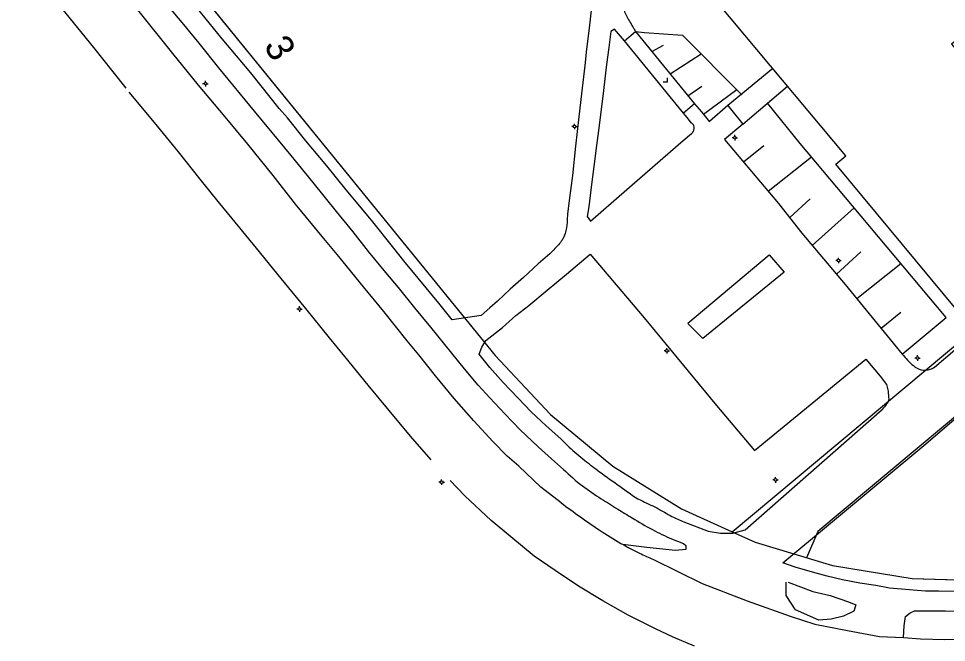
# Model space of a CAD drawing. Extents: x 1517229 to 1518128, y 6494851 to 6495271.
# Drawn here: x 1517641.4 to 1517777.6, y 6494938.3 to 6495029.8 of the extents above; entities that cross this region are included whole.
import ezdxf

# ---------------------------------------------------------------- set-up
doc = ezdxf.new("R2010")
doc.units = 0
doc.layers.add('Karta', color=7, linetype='Continuous')

msp = doc.modelspace()

# ---------------------------------------------------------------- linework, layer by layer
at = {"layer": 'Karta'}
for p, q in [((1517746.18, 6494954.49), (1517858.73, 6495048.55)), ((1517657.21, 6495046.87), (1517711.4, 6494980.36)), ((1517864, 6495042.53), (1517758.73, 6494954.55)), ((1517734.39, 6495024.95), (1517736.09, 6495025.88)), ((1517737.06, 6495021.68), (1517741.64, 6495024.6)), ((1517668.85, 6495020.44), (1517668.85, 6495020.64)), ((1517668.65, 6495020.24), (1517668.45, 6495020.24)), ((1517668.85, 6495020.04), (1517668.85, 6495019.84)), ((1517669.05, 6495020.24), (1517669.25, 6495020.24)), ((1517739.68, 6495018.48), (1517741.72, 6495019.9)), ((1517741.98, 6495015.75), (1517746.84, 6495019.4)), ((1517745.55, 6495017.02), (1517742.85, 6495014.7)), ((1517722.83, 6495013.96), (1517722.63, 6495013.96)), ((1517723.03, 6495014.16), (1517723.03, 6495014.36)), ((1517723.03, 6495013.76), (1517723.03, 6495013.56)), ((1517723.23, 6495013.96), (1517723.43, 6495013.96)), ((1517747.75, 6495014.28), (1517745.05, 6495012.04)), ((1517746.56, 6495012.52), (1517746.56, 6495012.72)), ((1517745.07, 6495012.05), (1517753, 6495002.66)), ((1517746.36, 6495012.32), (1517746.16, 6495012.32)), ((1517746.56, 6495012.12), (1517746.56, 6495011.92)), ((1517746.76, 6495012.32), (1517746.96, 6495012.32)), ((1517747.83, 6495008.78), (1517750.81, 6495011.15)), ((1517751.45, 6495004.49), (1517757.8, 6495009.53)), ((1517754.62, 6495000.59), (1517757.64, 6495003.37)), ((1517757.92, 6494996.52), (1517764.06, 6495002.02)), ((1517721.85, 6494992.31), (1517725.35, 6494995.22)), ((1517761.48, 6494992.29), (1517765.06, 6494995.58)), ((1517761.77, 6494994.49), (1517761.77, 6494994.69)), ((1517761.57, 6494994.29), (1517761.37, 6494994.29)), ((1517761.77, 6494994.09), (1517761.77, 6494993.89)), ((1517761.97, 6494994.29), (1517762.17, 6494994.29)), ((1517764.46, 6494988.7), (1517770.92, 6494993.87)), ((1517682.48, 6494987.18), (1517682.28, 6494987.18)), ((1517682.68, 6494987.38), (1517682.68, 6494987.58)), ((1517682.68, 6494986.98), (1517682.68, 6494986.78)), ((1517682.88, 6494987.18), (1517683.08, 6494987.18)), ((1517768.03, 6494984.35), (1517770.92, 6494986.72)), ((1517736.4, 6494981.06), (1517736.2, 6494981.06)), ((1517736.6, 6494981.26), (1517736.6, 6494981.46)), ((1517736.8, 6494981.06), (1517737, 6494981.06)), ((1517711.4, 6494980.36), (1517719.49, 6494971.68)), ((1517736.6, 6494980.86), (1517736.6, 6494980.66)), ((1517773.18, 6494979.99), (1517772.98, 6494979.99)), ((1517773.38, 6494980.19), (1517773.38, 6494980.39)), ((1517773.38, 6494979.79), (1517773.38, 6494979.59)), ((1517773.58, 6494979.99), (1517773.78, 6494979.99)), ((1517719.49, 6494971.68), (1517728.65, 6494964.14)), ((1517748.08, 6494954.76), (1517768.2, 6494972.45)), ((1517722.24, 6494966.93), (1517721.01, 6494968.14)), ((1517728.65, 6494964.14), (1517738.73, 6494957.86)), ((1517703.53, 6494961.98), (1517703.53, 6494962.18)), ((1517752.35, 6494962.1), (1517752.15, 6494962.1)), ((1517752.55, 6494962.3), (1517752.55, 6494962.5)), ((1517752.75, 6494962.1), (1517752.95, 6494962.1)), ((1517703.33, 6494961.78), (1517703.13, 6494961.78)), ((1517703.53, 6494961.58), (1517703.53, 6494961.38)), ((1517703.73, 6494961.78), (1517703.93, 6494961.78)), ((1517752.55, 6494961.9), (1517752.55, 6494961.7)), ((1517738.73, 6494957.86), (1517746.18, 6494954.49)), ((1517746.18, 6494954.49), (1517749.54, 6494952.96)), ((1517758.73, 6494954.55), (1517757.07, 6494950.69)), ((1517749.54, 6494952.96), (1517760.9, 6494949.53)), ((1517760.9, 6494949.53), (1517772.62, 6494947.63)), ((1517772.62, 6494947.63), (1517784.48, 6494947.28))]:
    msp.add_line(p, q, dxfattribs=at)
for points in [[(1517734.98, 6495043.01), (1517776.72, 6495077.67), (1517783.24, 6495069.88), (1517783.9, 6495070.37), (1517795.96, 6495055.9), (1517795.29, 6495055.3), (1517801.2, 6495048.09), (1517781.99, 6495032.2), (1517783.57, 6495030.27), (1517778.38, 6495026.04), (1517786.33, 6495016.68), (1517792.23, 6495021.58), (1517801.35, 6495010.73), (1517789.98, 6495001.11), (1517792.38, 6494998.21), (1517779.06, 6494987.16), (1517761.38, 6495008.42), (1517762.85, 6495009.67), (1517734.97, 6495043.01)], [(1517657.21, 6495046.87), (1517711.4, 6494980.36), (1517719.49, 6494971.68), (1517728.65, 6494964.14), (1517738.73, 6494957.86)], [(1517657.21, 6495019.59), (1517655.3, 6495021.99), (1517652.46, 6495025.53), (1517648.43, 6495030.54), (1517644.3, 6495035.55), (1517641.43, 6495039.12)], [(1517676.06, 6495016.19), (1517670.83, 6495022.55), (1517667.92, 6495026.2), (1517665.44, 6495029.21), (1517662.49, 6495032.75), (1517660.15, 6495035.66)], [(1517679.66, 6495016.62), (1517675.52, 6495021.82), (1517671.32, 6495026.83), (1517667.5, 6495031.52), (1517663.82, 6495035.97)], [(1517725.9, 6495034.88), (1517725.54, 6495031.49), (1517725.18, 6495028.4), (1517724.79, 6495025.32), (1517724.53, 6495022.91)], [(1517667.85, 6495020.03), (1517664.09, 6495024.69), (1517658.94, 6495031.07), (1517657.21, 6495033.2)], [(1517730.39, 6495026.54), (1517728.89, 6495028.25), (1517728.37, 6495027.88), (1517728.08, 6495025.55), (1517727.75, 6495023.06)], [(1517730.39, 6495026.54), (1517732.01, 6495027.91), (1517731.99, 6495027.88), (1517740.66, 6495017.28), (1517739.01, 6495015.93), (1517730.39, 6495026.54)], [(1517731.99, 6495027.89), (1517733.29, 6495027.73), (1517738.9, 6495027.34), (1517747.61, 6495018.63)], [(1517724.53, 6495022.91), (1517724.07, 6495018.76), (1517723.68, 6495015.36), (1517723.16, 6495011.09)], [(1517727.75, 6495023.06), (1517727.2, 6495018.42), (1517726.56, 6495013.37), (1517726.24, 6495011.19)], [(1517752.13, 6495022.48), (1517745.55, 6495017.02), (1517747.75, 6495014.28), (1517754.31, 6495019.88)], [(1517736.07, 6495020.5), (1517736.67, 6495020.5), (1517736.67, 6495021.1)], [(1517682.08, 6495002.58), (1517678.78, 6495006.78), (1517675.07, 6495011.37), (1517671.74, 6495015.4), (1517667.85, 6495020.03)], [(1517670.71, 6495002.98), (1517668.1, 6495006.22), (1517664.91, 6495010.25), (1517661.37, 6495014.53), (1517657.67, 6495019.01)], [(1517696.49, 6494996.12), (1517693.23, 6495000.2), (1517689.52, 6495004.65), (1517686.68, 6495008.19), (1517683.6, 6495011.86), (1517680.9, 6495015.23), (1517679.66, 6495016.62)], [(1517740.66, 6495017.28), (1517741.68, 6495016.13), (1517742.84, 6495014.64)], [(1517763.83, 6495002.3), (1517756.18, 6495011.48), (1517751.42, 6495017.33)], [(1517692.77, 6494995.63), (1517690.53, 6494998.51), (1517688.08, 6495001.49), (1517684.65, 6495005.73), (1517681.46, 6495009.69), (1517678.63, 6495013.07), (1517676.06, 6495016.19)], [(1517740.2, 6495014.47), (1517739.56, 6495015.26), (1517739.01, 6495015.93)], [(1517725.39, 6495000.07), (1517732.61, 6495006.4), (1517738.98, 6495011.89), (1517740.22, 6495012.93)], [(1517723.16, 6495011.09), (1517722.72, 6495006.76), (1517722.33, 6495003.83), (1517722, 6495001.16), (1517721.97, 6495000.25)], [(1517726.24, 6495011.19), (1517725.86, 6495008.08), (1517725.47, 6495005.05), (1517725.16, 6495002.17), (1517724.87, 6495000.74), (1517725.39, 6495000.07)], [(1517753.6, 6494949.92), (1517774.58, 6494967.4), (1517787.02, 6494978.07), (1517817.61, 6495004.85), (1517813.1, 6495011.01)], [(1517687.06, 6494982.93), (1517683.6, 6494987.27), (1517679.99, 6494991.65), (1517676.35, 6494996.13), (1517672.78, 6495000.44), (1517670.71, 6495002.98)], [(1517698.47, 6494982.51), (1517695.05, 6494986.81), (1517692.08, 6494990.42), (1517688.43, 6494994.91), (1517686.24, 6494997.54), (1517682.08, 6495002.58)], [(1517753, 6495002.66), (1517756.42, 6494998.31), (1517762.74, 6494990.79), (1517771.13, 6494980.58)], [(1517771.13, 6494980.58), (1517777.61, 6494985.92), (1517763.83, 6495002.3)], [(1517719.43, 6494995.29), (1517717.68, 6494993.82), (1517715.54, 6494991.82), (1517713.58, 6494990.11), (1517711.73, 6494988.32), (1517710.6, 6494987.37), (1517709.34, 6494986.25), (1517705.07, 6494985.59), (1517703.11, 6494988.04), (1517701.25, 6494990.28), (1517698, 6494994.26), (1517696.49, 6494996.12)], [(1517699.6, 6494987.34), (1517697.18, 6494990.34), (1517695.36, 6494992.52), (1517692.77, 6494995.63)], [(1517725.35, 6494995.22), (1517733.25, 6494985.87), (1517743.88, 6494973.01)], [(1517739.68, 6494985.09), (1517751.6, 6494995.15), (1517753.83, 6494992.61), (1517741.86, 6494982.86), (1517739.68, 6494985.04)], [(1517716.33, 6494987.72), (1517719.01, 6494989.93), (1517721.85, 6494992.31)], [(1517717.68, 6494966.98), (1517715.07, 6494969.43), (1517712.83, 6494971.82), (1517710.59, 6494974.13), (1517708.91, 6494975.99), (1517706.87, 6494978.4), (1517705.05, 6494980.72), (1517702.99, 6494983.24), (1517701.92, 6494984.51), (1517699.6, 6494987.34)], [(1517721.01, 6494968.14), (1517718.85, 6494970.06), (1517716.68, 6494972.1), (1517714.69, 6494974.13), (1517712.55, 6494976.41), (1517710.59, 6494978.58), (1517709.05, 6494980.58), (1517709.43, 6494981.59), (1517710.03, 6494982.57), (1517712.44, 6494984.47), (1517714.44, 6494986.22), (1517716.33, 6494987.72)], [(1517775.86, 6494978.65), (1517781.86, 6494983.74), (1517779.06, 6494987.16)], [(1517701.99, 6494965.05), (1517698.98, 6494968.52), (1517695.82, 6494972.31), (1517692.74, 6494976.02), (1517689.34, 6494980.19), (1517687.06, 6494982.93)], [(1517713.16, 6494965.58), (1517711.06, 6494967.72), (1517708.26, 6494970.76), (1517705.35, 6494974.06), (1517702.65, 6494977.39), (1517700.2, 6494980.44), (1517698.47, 6494982.51)], [(1517743.88, 6494973.01), (1517749.45, 6494966.43), (1517765.82, 6494979.8)], [(1517765.82, 6494979.8), (1517767.9, 6494977.31), (1517768.83, 6494976.12), (1517769.09, 6494975.14), (1517769.14, 6494974.2)], [(1517721.43, 6494963.63), (1517719.68, 6494965.19), (1517717.68, 6494966.98)], [(1517721.06, 6494958.75), (1517718.07, 6494961.02), (1517714.84, 6494964.11), (1517713.16, 6494965.58)], [(1517717.12, 6494950.93), (1517713.69, 6494953.74), (1517710.82, 6494956.15), (1517706.92, 6494959.76), (1517704.76, 6494962.02)], [(1517749.54, 6494952.96), (1517760.9, 6494949.53), (1517772.62, 6494947.63), (1517784.48, 6494947.28), (1517907.3, 6494951.79), (1517915.47, 6494952.77), (1517923.36, 6494955.07), (1517930.77, 6494958.64)], [(1517738.73, 6494957.86), (1517746.18, 6494954.49), (1517749.54, 6494952.96)], [(1517739.06, 6494955.95), (1517742.66, 6494954.61), (1517744.47, 6494954.31), (1517746.27, 6494954.31), (1517748.08, 6494954.76)], [(1517737.29, 6494953.45), (1517739.05, 6494952.8), (1517739.36, 6494952.5), (1517739.36, 6494951.9), (1517737.85, 6494951.75), (1517733.64, 6494952.2), (1517730.15, 6494952.63)], [(1517740.64, 6494937.69), (1517737.51, 6494939.02), (1517734.91, 6494940.25), (1517730.92, 6494942.24), (1517727.17, 6494944.35), (1517723.64, 6494946.52), (1517720.17, 6494948.8), (1517717.12, 6494950.93)], [(1517734.63, 6494950.43), (1517741.76, 6494946.93), (1517748.38, 6494944.38), (1517754.69, 6494942.12), (1517758.3, 6494940.92), (1517763.11, 6494940.02), (1517767.78, 6494939.11), (1517771.31, 6494938.96)], [(1517760.11, 6494947.96), (1517757.96, 6494948.55), (1517755.44, 6494949.29), (1517753.6, 6494949.92)], [(1517754.39, 6494947.09), (1517758, 6494945.73), (1517760.56, 6494945.13), (1517763.26, 6494944.23), (1517764.32, 6494943.78), (1517764.02, 6494942.87), (1517762.51, 6494942.12), (1517760.71, 6494941.67), (1517758.9, 6494941.52), (1517755.45, 6494943.02), (1517754.09, 6494945.13), (1517754.09, 6494947.09)], [(1517773.34, 6494945.89), (1517771.64, 6494946.03), (1517769.29, 6494946.24), (1517767.26, 6494946.59), (1517764.91, 6494946.94), (1517762.39, 6494947.43), (1517760.11, 6494947.96)], [(1517801.88, 6494946.07), (1517799.82, 6494946.03), (1517797.47, 6494945.96), (1517793.76, 6494945.89), (1517790.01, 6494945.82), (1517786.44, 6494945.85), (1517783.04, 6494945.82), (1517779.85, 6494945.71), (1517776.49, 6494945.78), (1517774.56, 6494945.78), (1517773.34, 6494945.89)], [(1517771.31, 6494938.96), (1517771.42, 6494940.68), (1517771.63, 6494942.08), (1517772.29, 6494942.61), (1517772.96, 6494942.92), (1517777.48, 6494942.92), (1517782.1, 6494942.82), (1517788.02, 6494942.82), (1517792.82, 6494942.85)], [(1517771.31, 6494938.96), (1517773.83, 6494938.79), (1517777.37, 6494938.69), (1517781.24, 6494938.72), (1517786.9, 6494938.72), (1517790.78, 6494938.93), (1517793.13, 6494939.04)]]:
    msp.add_lwpolyline(points, dxfattribs=at)
for centre in [(1517668.85, 6495020.24), (1517723.03, 6495013.96), (1517746.56, 6495012.32), (1517761.77, 6494994.29), (1517682.68, 6494987.18), (1517736.6, 6494981.06), (1517773.38, 6494979.99), (1517703.53, 6494961.78), (1517752.55, 6494962.1)]:
    msp.add_circle(centre, 0.2, dxfattribs=at)
for points in [[(1517729.04, 6495035.47), (1517729.51, 6495033.51), (1517730.08, 6495031.59), (1517730.75, 6495030.01), (1517731.71, 6495028.4), (1517731.99, 6495027.88)], [(1517740.22, 6495012.93), (1517740.48, 6495013.24), (1517740.59, 6495013.65), (1517740.56, 6495014.07), (1517740.19, 6495014.48)], [(1517721.97, 6495000.25), (1517721.78, 6494998.7), (1517721.47, 6494997.79), (1517721.21, 6494997.3), (1517720.69, 6494996.62), (1517719.99, 6494995.87), (1517719.43, 6494995.29)], [(1517771.13, 6494980.58), (1517772.77, 6494978.87), (1517773.91, 6494978.25), (1517775.25, 6494978.35), (1517775.98, 6494978.71)], [(1517769.14, 6494974.2), (1517769.13, 6494973.78), (1517768.85, 6494973.25), (1517768.2, 6494972.45)], [(1517722.24, 6494966.93), (1517724.53, 6494964.97), (1517726.71, 6494963.3), (1517729.68, 6494961.17), (1517732.75, 6494959.13), (1517735.1, 6494957.99), (1517737.34, 6494956.74), (1517739.06, 6494955.95)], [(1517721.43, 6494963.63), (1517724.21, 6494961.22), (1517726.97, 6494959.34), (1517729.37, 6494957.83), (1517731.5, 6494956.53), (1517734.47, 6494954.81), (1517737.29, 6494953.45)], [(1517721.06, 6494958.75), (1517723.9, 6494956.68), (1517727.08, 6494954.5), (1517730.26, 6494952.57), (1517732.55, 6494951.37), (1517734.63, 6494950.43)]]:
    msp.add_spline(points, degree=3, dxfattribs=at)

# ---------------------------------------------------------------- texts
msp.add_text('3', height=4, rotation=299.2317, dxfattribs=at).set_placement((1517677.36, 6495025.85))

doc.saveas('drawing.dxf')
